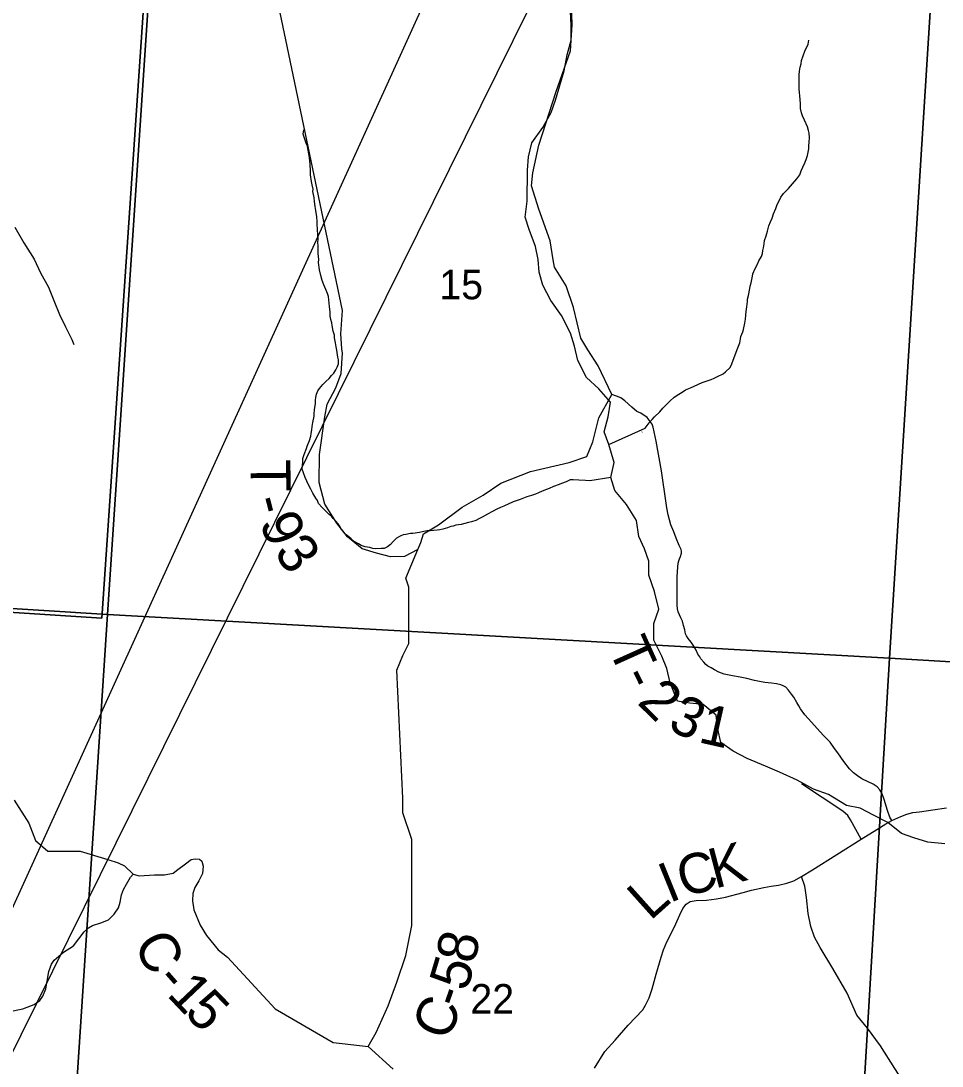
# Model space of a CAD drawing. Extents: x 0 to 45.4, y -2.2 to 22.
# Drawn here: x 5.991 to 7.301, y 17.524 to 19.01 of the extents above; entities that cross this region are included whole.
import ezdxf

# ---------------------------------------------------------------- set-up
doc = ezdxf.new("R2010")
doc.units = 0
for name, color, linetype in [('GM_X_Corporation', 7, 'Continuous'), ('GM_X_County_Road', 7, 'Continuous'), ('GM_X_County_Road_Text', 7, 'Continuous'), ('GM_X_Minor_River', 7, 'Continuous'), ('GM_X_Section_Text', 7, 'Continuous'), ('GM_X_Township_Road', 7, 'Continuous'), ('GM_X_Township_Road_Text', 7, 'Continuous'), ('SH_Text', 7, 'Continuous')]:
    doc.layers.add(name, color=color, linetype=linetype)

msp = doc.modelspace()

# ---------------------------------------------------------------- linework, layer by layer
at = {"layer": 'GM_X_Corporation'}
for points in [[(5.642, 18.1908), (6.1061, 18.1607), (6.1763, 19.1885), (6.181, 19.2539), (6.2236, 19.8542), (6.2346, 20.0088), (6.2538, 20.2076), (6.2588, 20.2929), (6.2789, 20.7002), (6.2882, 20.8226), (6.2942, 20.9), (2.1, 20.9)], [(5.6021, 14.1), (7.0413, 14.1), (7.1146, 14.1136), (7.5608, 14.2194), (7.6244, 14.2444), (8.0832, 14.3972), (8.4711, 14.5406), (8.5907, 14.5823), (8.8228, 14.6772), (8.9, 14.7192), (8.9, 20.9), (6.2942, 20.9), (6.2882, 20.8226), (6.2789, 20.7002), (6.2588, 20.2929), (6.2538, 20.2076), (6.2346, 20.0088), (6.2236, 19.8542), (6.181, 19.2539), (6.1763, 19.1885), (6.1061, 18.1607), (5.642, 18.1908)]]:
    msp.add_lwpolyline(points, dxfattribs=at)
for points in [[(6.1827, 19.1954), (6.1142, 18.166), (5.0121, 18.2353), (5.073, 19.2613)], [(7.2905, 19.1287), (7.2262, 18.1039), (6.1142, 18.166), (6.1827, 19.1954)], [(8.3794, 19.064), (8.3245, 18.0384), (7.2262, 18.1039), (7.2905, 19.1287)], [(5.0121, 18.2353), (6.1142, 18.166), (6.0488, 17.1677), (4.9524, 17.2347)], [(6.1142, 18.166), (7.2262, 18.1039), (7.1661, 17.098), (6.0488, 17.1677)], [(7.2262, 18.1039), (8.3245, 18.0384), (8.2701, 17.0306), (7.1661, 17.098)]]:
    msp.add_lwpolyline(points, close=True, dxfattribs=at)
at = {"layer": 'GM_X_County_Road'}
for points in [[(6.4847, 17.5519), (6.4961, 17.5717), (6.513, 17.6097), (6.5257, 17.6434), (6.5383, 17.6814), (6.5468, 17.7237), (6.5468, 17.8461), (6.5341, 17.884), (6.5341, 17.9051), (6.5257, 18.0866), (6.5341, 18.1077), (6.5425, 18.1246), (6.5425, 18.2048), (6.5383, 18.2174), (6.5553, 18.2582), (6.5594, 18.2681), (6.5636, 18.2808), (6.5847, 18.2934), (6.6185, 18.3187), (6.6481, 18.3356), (6.6734, 18.3525), (6.7156, 18.3694), (6.7704, 18.382), (6.7957, 18.3905), (6.8042, 18.4116), (6.8126, 18.4453), (6.831, 18.4788), (6.8117, 18.5196), (6.7973, 18.5423), (6.787, 18.5588), (6.7767, 18.6021), (6.7664, 18.633), (6.7499, 18.6598), (6.7478, 18.6701), (6.7437, 18.6969), (6.7272, 18.7423), (6.7169, 18.7753), (6.7189, 18.7939), (6.7272, 18.833), (6.7519, 18.9094), (6.7726, 18.9671), (6.7746, 19.0042), (6.7705, 19.1341)], [(5.9812, 17.9022), (6.0023, 17.8696), (6.0119, 17.8447), (6.0291, 17.8294), (6.075, 17.8294), (6.1145, 17.8177), (6.1293, 17.813), (6.1382, 17.8086), (6.1507, 17.7968), (6.1593, 17.7943), (6.1811, 17.7957), (6.1952, 17.7957), (6.2073, 17.7984), (6.2143, 17.8034), (6.2251, 17.8117), (6.233, 17.8175), (6.2388, 17.8188), (6.245, 17.818), (6.248, 17.8155), (6.25, 17.8084), (6.2492, 17.7976), (6.2438, 17.7872), (6.2384, 17.7777), (6.2355, 17.7694), (6.2347, 17.759), (6.2367, 17.7462), (6.2459, 17.7242), (6.2546, 17.7096), (6.2716, 17.6893), (6.2845, 17.6789), (6.3526, 17.6054), (6.435, 17.5576), (6.4479, 17.5561)], [(6.8065, 17.5212), (6.8214, 17.5447), (6.8357, 17.5611), (6.8543, 17.5821), (6.8751, 17.6039), (6.8793, 17.6106), (6.8845, 17.6209), (6.8887, 17.6338), (6.8941, 17.6549), (6.9013, 17.6788), (6.9047, 17.6893), (6.9095, 17.7005), (6.9203, 17.7219), (6.928, 17.7392), (6.9322, 17.7483), (6.9367, 17.7543), (6.9424, 17.7578), (6.9513, 17.7595), (6.9659, 17.7601), (6.9799, 17.7617), (6.9926, 17.7642), (7.0178, 17.7706), (7.03, 17.7741), (7.0471, 17.7778), (7.0577, 17.7797), (7.0684, 17.7811), (7.0801, 17.784), (7.0902, 17.7876), (7.1008, 17.7934), (7.1164, 17.8031), (7.1855, 17.8466), (7.2079, 17.8604), (7.2208, 17.8684), (7.2293, 17.873), (7.2423, 17.8789), (7.2508, 17.882), (7.259, 17.8843), (7.2687, 17.8854), (7.2877, 17.8883), (7.3069, 17.8914)], [(7.3085, 17.4131), (7.2883, 17.4399), (7.2792, 17.4506), (7.2589, 17.4816), (7.2475, 17.4993), (7.2335, 17.5206), (7.2132, 17.5527), (7.1949, 17.5781), (7.1795, 17.5964), (7.166, 17.6277), (7.1453, 17.6629), (7.1275, 17.6925), (7.1195, 17.7075), (7.114, 17.7227), (7.1102, 17.7411), (7.1078, 17.7635), (7.1067, 17.7735), (7.1058, 17.7799), (7.1008, 17.7934)], [(6.4479, 17.5561), (6.4847, 17.5519), (6.5204, 17.5195)]]:
    msp.add_lwpolyline(points, dxfattribs=at)
at = {"layer": 'GM_X_Minor_River'}
for points in [[(7.3046, 17.8402), (7.2804, 17.8426), (7.2607, 17.8487), (7.2433, 17.8549), (7.2237, 17.8701), (7.2033, 17.8808), (7.1844, 17.8908), (7.1647, 17.8946), (7.1391, 17.9099), (7.1179, 17.9176), (7.0945, 17.9306), (7.0695, 17.942), (7.0499, 17.9505), (7.0234, 17.9612), (7.0037, 17.9719), (6.9864, 17.9841), (6.9819, 18.0031), (6.9797, 18.0228), (6.9609, 18.0381), (6.9419, 18.0397), (6.9245, 18.0428), (6.914, 18.0686), (6.9096, 18.0892), (6.9021, 18.1066), (6.8908, 18.1295), (6.8909, 18.153), (6.8978, 18.1735), (6.8918, 18.1986), (6.8836, 18.2221), (6.8837, 18.2419), (6.8777, 18.2594), (6.8695, 18.2769), (6.8665, 18.2996), (6.8522, 18.3225), (6.8356, 18.3423), (6.8297, 18.3605), (6.8343, 18.3818), (6.8268, 18.4076), (6.8201, 18.4258), (6.8262, 18.4471), (6.8294, 18.4676), (6.8128, 18.4866), (6.7954, 18.5026), (6.7827, 18.527), (6.7782, 18.5475), (6.7722, 18.5657), (6.7594, 18.5908), (6.7444, 18.6121), (6.7331, 18.6342), (6.7279, 18.6524), (6.7265, 18.6706), (6.7227, 18.6889), (6.7138, 18.7132), (6.7078, 18.7307), (6.7109, 18.7535), (6.7111, 18.7975), (6.7127, 18.8165), (6.7173, 18.8362), (6.7333, 18.8581), (6.7448, 18.8794), (6.7509, 18.8968), (6.7632, 18.9385), (6.7678, 18.9613), (6.7732, 18.9825), (6.7733, 19.0038), (6.7726, 19.0227)], [(7.0991, 18.9441), (7.1003, 18.9486), (7.1011, 18.9532), (7.1031, 18.96), (7.1055, 18.9668), (7.1102, 18.9766), (7.1111, 18.9823)], [(6.8268, 18.4076), (6.8787, 18.431), (6.8814, 18.4344), (6.8845, 18.4385), (6.8884, 18.443), (6.8918, 18.4467), (6.8995, 18.4542), (6.9038, 18.4591), (6.9084, 18.4639), (6.9138, 18.4691), (6.92, 18.4747), (6.9265, 18.4792), (6.9311, 18.4821), (6.9361, 18.4851), (6.9429, 18.488), (6.9483, 18.4906), (6.9597, 18.4957), (6.9666, 18.4983), (6.9723, 18.5001), (6.9765, 18.5019), (6.9815, 18.5041), (6.9895, 18.5081), (6.993, 18.5111), (6.9995, 18.5171), (7.0019, 18.5223), (7.0039, 18.5276), (7.0062, 18.5337), (7.0078, 18.539), (7.0102, 18.545), (7.013, 18.5522), (7.0142, 18.5578), (7.0147, 18.5612), (7.0174, 18.5676), (7.0186, 18.571), (7.0203, 18.5801), (7.0212, 18.5858), (7.0216, 18.5915), (7.0221, 18.5968), (7.023, 18.6032), (7.0243, 18.6108), (7.0243, 18.6142), (7.0255, 18.6195), (7.0276, 18.6294), (7.0277, 18.6328), (7.0293, 18.6373), (7.0313, 18.6468), (7.0318, 18.6502), (7.0349, 18.6577), (7.0377, 18.663), (7.0404, 18.6687), (7.0439, 18.675), (7.0452, 18.6792), (7.046, 18.6834), (7.0468, 18.6872), (7.0477, 18.6928), (7.0485, 18.6974), (7.0505, 18.7042), (7.0525, 18.7106), (7.0546, 18.7182), (7.0569, 18.7242), (7.0593, 18.7295), (7.0613, 18.7355), (7.0645, 18.7431), (7.0665, 18.7487), (7.0688, 18.7532), (7.0716, 18.7589), (7.0754, 18.7645), (7.0824, 18.7716), (7.0882, 18.778), (7.0944, 18.7851), (7.0983, 18.7907), (7.1006, 18.7967), (7.103, 18.802), (7.1054, 18.8077), (7.1074, 18.8126), (7.1094, 18.8182), (7.1106, 18.8232), (7.1114, 18.8277), (7.1115, 18.8319), (7.112, 18.8372), (7.1121, 18.844), (7.1118, 18.8501), (7.1107, 18.8539), (7.1093, 18.8593), (7.1053, 18.8688), (7.1024, 18.8749), (7.101, 18.8791), (7.0995, 18.8852), (7.0993, 18.8917), (7.099, 18.8978), (7.0978, 18.913), (7.0975, 18.9202), (7.0977, 18.9331), (7.0982, 18.938), (7.0991, 18.9441)], [(6.4079, 18.4514), (6.4083, 18.4567), (6.4096, 18.4658), (6.4097, 18.4704), (6.4105, 18.4746), (6.4114, 18.4791), (6.413, 18.484), (6.4153, 18.4874), (6.4203, 18.493), (6.4246, 18.4971), (6.4292, 18.5012), (6.4327, 18.5057), (6.4358, 18.5091), (6.4389, 18.5136), (6.4408, 18.5174), (6.4424, 18.5223), (6.4425, 18.528), (6.4418, 18.5318), (6.4404, 18.5382), (6.4401, 18.5417), (6.4394, 18.5466), (6.4384, 18.5523), (6.437, 18.5592), (6.4367, 18.563), (6.4349, 18.5687), (6.4335, 18.5767), (6.4332, 18.5805), (6.4318, 18.5851), (6.4307, 18.5901), (6.4305, 18.5958), (6.4299, 18.6037), (6.4282, 18.6178), (6.4271, 18.622), (6.4246, 18.6281), (6.4217, 18.6346), (6.4195, 18.6408), (6.4174, 18.6476), (6.4156, 18.656), (6.4143, 18.6663), (6.4144, 18.6705), (6.4138, 18.6792), (6.4136, 18.6906), (6.4133, 18.6944), (6.4134, 18.7001), (6.4131, 18.7058), (6.4125, 18.713), (6.4122, 18.7206), (6.4123, 18.7244), (6.4116, 18.7313), (6.4103, 18.74), (6.4092, 18.7457), (6.4082, 18.753), (6.408, 18.7587), (6.4062, 18.7671), (6.4063, 18.7705), (6.4052, 18.7766), (6.4042, 18.7815), (6.4029, 18.791), (6.4026, 18.7975), (6.4023, 18.8047), (6.4017, 18.8112), (6.4007, 18.8184), (6.399, 18.8283), (6.3986, 18.8317), (6.3964, 18.836), (6.3939, 18.8444), (6.3925, 18.8489), (6.3934, 18.8546)], [(5.9822, 18.7165), (5.9949, 18.6944), (6.01, 18.6708), (6.019, 18.6518), (6.0303, 18.6313), (6.0378, 18.6123), (6.046, 18.5925), (6.0543, 18.575), (6.0633, 18.5568), (6.0663, 18.5499)], [(6.8297, 18.3605), (6.8001, 18.356), (6.7937, 18.3565), (6.7842, 18.357), (6.7762, 18.3575), (6.7721, 18.3572), (6.7663, 18.3543), (6.7595, 18.3521), (6.7561, 18.3506), (6.7484, 18.3477), (6.7423, 18.3452), (6.7385, 18.3437), (6.732, 18.3412), (6.7267, 18.339), (6.7225, 18.3372), (6.7172, 18.3353), (6.7103, 18.3332), (6.7008, 18.3295), (6.6908, 18.3259), (6.6775, 18.3201), (6.6729, 18.3182), (6.6676, 18.3157), (6.6614, 18.3124), (6.6546, 18.3087), (6.6469, 18.3042), (6.6423, 18.302), (6.6377, 18.2995), (6.6316, 18.2977), (6.6275, 18.2966), (6.6168, 18.2941), (6.6096, 18.2927), (6.6058, 18.2916), (6.6024, 18.2909), (6.5974, 18.2891), (6.5909, 18.2873), (6.5864, 18.2863), (6.5826, 18.2856), (6.5776, 18.2853), (6.5731, 18.285), (6.5685, 18.2847), (6.564, 18.284), (6.5575, 18.2826), (6.5484, 18.2812), (6.545, 18.2809), (6.5382, 18.2799), (6.5344, 18.2792), (6.5302, 18.2773), (6.5252, 18.2744), (6.5202, 18.2699), (6.5163, 18.2654), (6.5121, 18.2621), (6.5075, 18.2599), (6.5033, 18.2596), (6.4958, 18.2593), (6.4912, 18.2598), (6.4871, 18.261), (6.4803, 18.2622), (6.4746, 18.2642), (6.4709, 18.2662), (6.4649, 18.2697), (6.4604, 18.2736), (6.4548, 18.2782), (6.4507, 18.2821), (6.447, 18.2863), (6.4448, 18.2905), (6.4422, 18.2948), (6.4389, 18.2986), (6.4351, 18.3025), (6.4326, 18.3059), (6.4292, 18.3083), (6.4258, 18.3114), (6.4225, 18.3148), (6.4191, 18.3179), (6.4139, 18.3237), (6.4125, 18.3279), (6.4103, 18.3314), (6.4062, 18.3383), (6.4033, 18.344), (6.4004, 18.3494), (6.3975, 18.3555), (6.3953, 18.3609), (6.3927, 18.3674), (6.3909, 18.3727), (6.3919, 18.383), (6.392, 18.3875), (6.3939, 18.3932), (6.3971, 18.4019), (6.3979, 18.4053), (6.4015, 18.4132), (6.4031, 18.4192), (6.4039, 18.4234), (6.4048, 18.4283), (6.4053, 18.4333), (6.4061, 18.4389), (6.4078, 18.448), (6.4079, 18.4514)], [(6.8742, 18.4254), (6.8738, 18.4253)]]:
    msp.add_lwpolyline(points, dxfattribs=at)
at = {"layer": 'GM_X_Township_Road'}
for points in [[(6.4474, 18.5435), (6.4457, 18.5649), (6.448, 18.5979), (6.3487, 19.0736), (6.3818, 19.0929), (6.3914, 19.0999)], [(6.5553, 18.2582), (6.5365, 18.2483), (6.5165, 18.2479), (6.4964, 18.2529), (6.4763, 18.2593), (6.4551, 18.2764), (6.44, 18.2958), (6.4233, 18.3227), (6.415, 18.3535), (6.4157, 18.3933), (6.4229, 18.4469), (6.4264, 18.4647), (6.4389, 18.4882), (6.4461, 18.5083), (6.448, 18.5372), (6.4474, 18.5435)], [(7.2293, 17.873), (7.2267, 17.8779), (7.2231, 17.8872), (7.2186, 17.9028), (7.2154, 17.9112), (7.2124, 17.9168), (7.2083, 17.9208), (7.2027, 17.9249), (7.1955, 17.9282), (7.1869, 17.9323), (7.1806, 17.9367), (7.1746, 17.9408), (7.1691, 17.9468), (7.1611, 17.9568), (7.1526, 17.9693), (7.1477, 17.9753), (7.1415, 17.9843), (7.1318, 17.9945), (7.1153, 18.0128), (7.1056, 18.0233), (7.0997, 18.032), (7.097, 18.0362), (7.0942, 18.041), (7.0901, 18.0483), (7.0869, 18.0527), (7.0826, 18.0584), (7.0785, 18.0628), (7.0747, 18.0648), (7.0717, 18.066), (7.0655, 18.0672), (7.0584, 18.0682), (7.0488, 18.0694), (7.041, 18.0708), (7.034, 18.072), (7.0231, 18.0751), (7.0135, 18.077), (7.0027, 18.0788), (6.9907, 18.0813), (6.9834, 18.0842), (6.977, 18.0875), (6.9723, 18.0901), (6.9679, 18.0927), (6.9649, 18.0948), (6.9621, 18.098), (6.9578, 18.1031), (6.9562, 18.1056), (6.9537, 18.1095), (6.9513, 18.1152), (6.9476, 18.1211), (6.9439, 18.1264), (6.9399, 18.1317), (6.9376, 18.1354), (6.936, 18.1387), (6.9349, 18.1444), (6.9332, 18.1501), (6.9315, 18.1565), (6.9295, 18.1611), (6.9273, 18.1654), (6.9254, 18.1696), (6.9245, 18.1739), (6.9243, 18.1793), (6.924, 18.1905), (6.9243, 18.2044), (6.9241, 18.2197), (6.925, 18.2338), (6.9257, 18.2388), (6.9263, 18.2423), (6.9273, 18.2449), (6.929, 18.2483), (6.9301, 18.2529), (6.9302, 18.2553), (6.9297, 18.2584), (6.9271, 18.264), (6.9225, 18.2743), (6.9192, 18.2836), (6.9152, 18.2935), (6.913, 18.3007), (6.9115, 18.3078), (6.9095, 18.3176), (6.9086, 18.3244), (6.9018, 18.3701), (6.894, 18.4121), (6.89, 18.4324), (6.8886, 18.4366), (6.8815, 18.4459), (6.8724, 18.4522), (6.8668, 18.4546), (6.8594, 18.4608), (6.8499, 18.4698), (6.8439, 18.474), (6.8377, 18.4763), (6.831, 18.4788)], [(7.1855, 17.8466), (7.1705, 17.874), (7.1667, 17.8801), (7.1599, 17.8862), (7.1007, 17.9252)], [(5.9729, 17.6011), (5.9938, 17.6056), (6.0098, 17.6116), (6.0177, 17.6171), (6.0222, 17.6235), (6.0262, 17.634), (6.0307, 17.6584), (6.0346, 17.6689), (6.0381, 17.6748), (6.0516, 17.6858), (6.0655, 17.6952), (6.0809, 17.7148), (6.0871, 17.7206), (6.0927, 17.7239), (6.1046, 17.7277), (6.1156, 17.732), (6.1234, 17.7399), (6.1295, 17.7491), (6.1322, 17.7569), (6.1338, 17.7675), (6.1367, 17.775), (6.1413, 17.7829), (6.1467, 17.7926), (6.1507, 17.7968)]]:
    msp.add_lwpolyline(points, dxfattribs=at)
at = {"layer": 'SH_Text'}
msp.add_lwpolyline([(7.4129, 20.9), (4.8173, 15.1976), (7.4129, 20.4406)], close=True, dxfattribs=at)

# ---------------------------------------------------------------- texts
at = {"layer": 'GM_X_County_Road_Text'}
for s, rotation, p in [('K', 14.6874, (6.9777, 17.7761)), ('C', 15.6334, (6.933, 17.7636)), ('I', 22.1094, (6.9129, 17.7554)), ('L', 41.8499, (6.8857, 17.7297)), ('C', 297.4188, (6.1502, 17.6982)), ('8', 78.9513, (6.6363, 17.6682)), ('5', 73.416, (6.6249, 17.6288)), ('-', 311.1509, (6.1801, 17.6445)), ('1', 313.4805, (6.1971, 17.625)), ('5', 314.1169, (6.2217, 17.5992)), ('C', 67.9757, (6.598, 17.5579)), ('-', 71.3134, (6.6167, 17.6045))]:
    msp.add_text(s, height=0.0568, rotation=rotation, dxfattribs=at).set_placement(p)
at = {"layer": 'GM_X_Section_Text'}
for s, p in [('15', (6.5858, 18.614)), ('22', (6.63, 17.5988))]:
    msp.add_text(s, height=0.04186, rotation=0, dxfattribs=at).set_placement(p)
at = {"layer": 'GM_X_Township_Road_Text'}
for s, rotation, p in [('T', 270.63, (6.3173, 18.3864)), ('-', 284.5573, (6.3197, 18.329)), ('9', 294.3067, (6.3291, 18.2965)), ('3', 305.529, (6.3495, 18.2541)), ('T', 294.2171, (6.8253, 18.1185)), ('-', 296.1005, (6.8436, 18.0779)), ('2', 315.2655, (6.8659, 18.0402)), ('3', 335.6918, (6.9089, 18.0031)), ('1', 347.2279, (6.9526, 17.9848))]:
    msp.add_text(s, height=0.0568, rotation=rotation, dxfattribs=at).set_placement(p)

doc.saveas('drawing.dxf')
